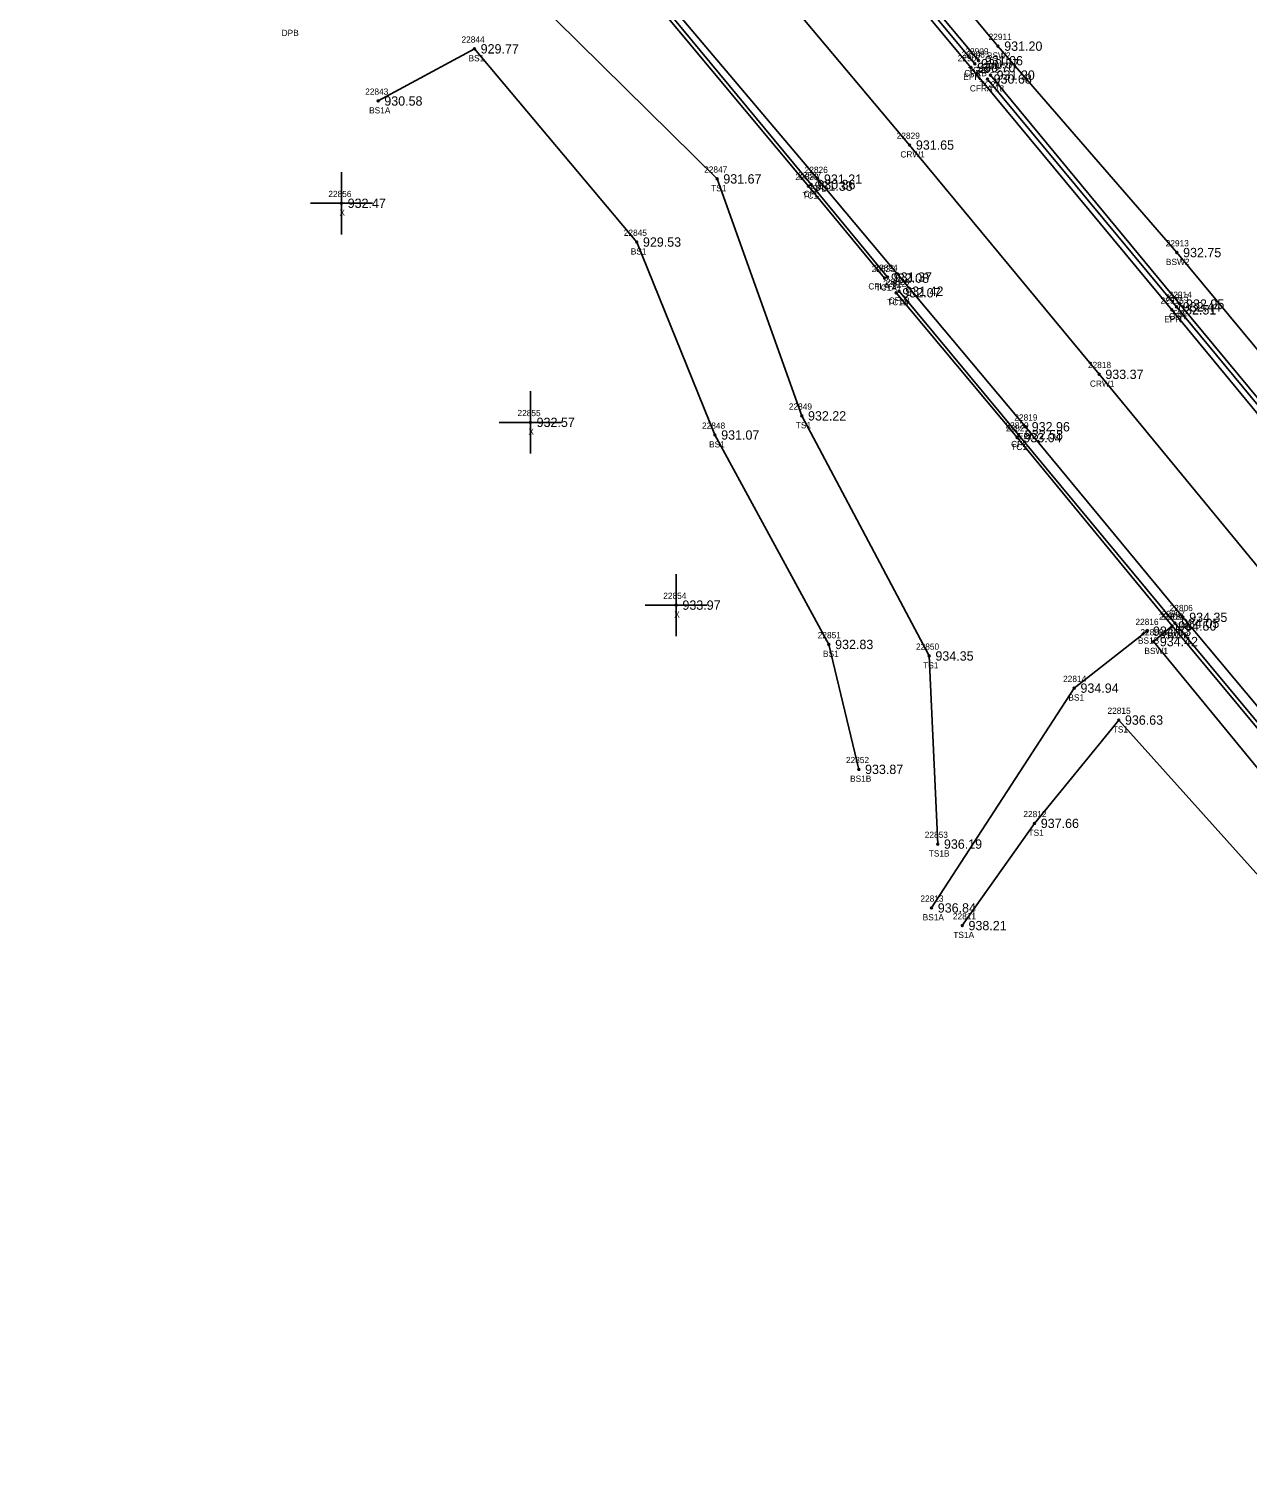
# Model space of a CAD drawing. Extents: x 1576181 to 1577685, y 1099396 to 1101490.
# Drawn here: x 1576232.8 to 1576428.7, y 1099850.9 to 1100084.5 of the extents above; entities that cross this region are included whole.
import ezdxf

# ---------------------------------------------------------------- set-up
doc = ezdxf.new("R2010")
doc.units = 0
for name, color, linetype in [('RD_DTM_BkLn1', 7, 'Continuous'), ('RD_DTM_BkLn2', 7, 'Continuous'), ('RD_DTM_BkLn_txCode', 7, 'Continuous'), ('RD_EX_Conc', 7, 'Continuous'), ('RD_EX_Conc_txCode', 7, 'Continuous'), ('RD_EX_Driveway_txCode', 7, 'Continuous'), ('RD_EX_Misc', 7, 'Continuous'), ('RD_EX_Misc_txCode', 7, 'Continuous'), ('RD_EX_Road', 7, 'Continuous'), ('RD_EX_Road_txCode', 7, 'Continuous'), ('RD_EX_TX_Conc_ELEV', 7, 'Continuous'), ('RD_EX_TX_Misc_ELEV', 7, 'Continuous'), ('RD_EX_TX_Road_ELEV', 7, 'Continuous'), ('RD_HC_Survey_ELEV', 7, 'Continuous'), ('RD_HC_Survey_txCode', 7, 'Continuous'), ('RD_SMD_Locator', 7, 'Continuous')]:
    doc.layers.add(name, color=color, linetype=linetype)

msp = doc.modelspace()

# ---------------------------------------------------------------- linework, layer by layer
at = {"layer": 'RD_DTM_BkLn1'}
msp.add_lwpolyline([(1576552.2, 1099850.88), (1576529.87, 1099877.59), (1576499.35, 1099914.67), (1576467.87, 1099952.97), (1576435.79, 1099991.46), (1576404.79, 1100029.02), (1576374.33, 1100065.86), (1576340.53, 1100106.05), (1576310.27, 1100142.66), (1576276.25, 1100183.58), (1576243.14, 1100223.05)], dxfattribs=at)
at = {"layer": 'RD_DTM_BkLn2'}
for points in [[(1576257.4, 1100233.36), (1576289.16, 1100194.59), (1576321.56, 1100155.93), (1576353.74, 1100117.24), (1576385.41, 1100079.42)], [(1576370.31, 1100044.47), (1576358.04, 1100059.26), (1576326.91, 1100096.57), (1576310.67, 1100115.96)], [(1576306.3, 1100096.99), (1576343.37, 1100060.42), (1576356.99, 1100022.34), (1576377.47, 1099983.76), (1576378.84, 1099953.53)], [(1576288.87, 1100072.94), (1576304.36, 1100081.32), (1576330.45, 1100050.27), (1576343.03, 1100019.27), (1576361.35, 1099985.61), (1576366.16, 1099965.54)], [(1576387.31, 1100077.1), (1576417.77, 1100040.31), (1576449.29, 1100002.34), (1576481.27, 1099963.75), (1576512.83, 1099926.03), (1576537.62, 1099896.34), (1576545.23, 1099890.59), (1576552.64, 1099888.11), (1576559.01, 1099887.38), (1576563.78, 1099887.59)], [(1576459.19, 1099937.38), (1576416.51, 1099988.58), (1576391.62, 1100018.84), (1576372.16, 1100042.12)], [(1576377.85, 1099943.27), (1576400.79, 1099978.59), (1576412.45, 1099987.74)], [(1576382.79, 1099940.43), (1576394.41, 1099956.86), (1576407.94, 1099973.46), (1576450.18, 1099926.39)]]:
    msp.add_lwpolyline(points, dxfattribs=at)
at = {"layer": 'RD_EX_Conc'}
for points in [[(1576260.63, 1100235.68), (1576292.32, 1100197.24), (1576324.7, 1100158.41), (1576356.89, 1100119.84), (1576388.53, 1100081.75), (1576417.29, 1100048.58), (1576453.09, 1100005.48), (1576485.23, 1099966.78), (1576516.75, 1099929.08), (1576537.53, 1099904.47)], [(1576256.92, 1100232.94), (1576288.76, 1100194.24), (1576321.1, 1100155.62), (1576353.2, 1100116.85), (1576384.81, 1100078.92)], [(1576370.77, 1100044.65), (1576358.48, 1100059.51), (1576327.45, 1100097.03), (1576315.3, 1100111.52), (1576315.3, 1100111.52), (1576311.1, 1100116.47)], [(1576386.83, 1100076.47), (1576417.24, 1100039.86), (1576448.62, 1100001.94), (1576480.86, 1099963.28), (1576512.43, 1099925.58), (1576537.17, 1099895.97), (1576544.94, 1099889.99), (1576552.63, 1099887.59), (1576559.14, 1099887.04), (1576563.8, 1099887.09)], [(1576459.68, 1099937.85), (1576416.98, 1099989.02), (1576391.85, 1100019.32), (1576372.62, 1100042.37)], [(1576452.41, 1099925.37), (1576456.22, 1099930.46), (1576454.77, 1099932.3), (1576456.21, 1099934.19), (1576413.55, 1099986.07), (1576416.51, 1099988.58)]]:
    msp.add_lwpolyline(points, dxfattribs=at)
at = {"layer": 'RD_EX_Misc'}
for p, q in [((1576282.98, 1100051.5), (1576282.98, 1100061.5)), ((1576277.98, 1100056.5), (1576287.98, 1100056.5)), ((1576313.36, 1100016.3), (1576313.36, 1100026.3)), ((1576308.36, 1100021.3), (1576318.36, 1100021.3)), ((1576336.8, 1099986.93), (1576336.8, 1099996.93)), ((1576331.8, 1099991.93), (1576341.8, 1099991.93))]:
    msp.add_line(p, q, dxfattribs=at)
at = {"layer": 'RD_EX_Road'}
for points in [[(1576256.11, 1100232.37), (1576288, 1100193.74), (1576320.42, 1100155.1), (1576352.59, 1100116.23), (1576384.18, 1100078.33), (1576416.49, 1100039.38), (1576447.98, 1100001.18), (1576479.99, 1099962.6), (1576511.56, 1099924.96), (1576536.28, 1099895.31), (1576544.58, 1099889.25), (1576552.5, 1099886.45), (1576559.41, 1099885.67), (1576563.94, 1099885.9), (1576563.8, 1099887.09)], [(1576526.76, 1099857.36), (1576527.6, 1099858), (1576488.54, 1099905.39), (1576460.88, 1099939.06), (1576418.27, 1099989.97), (1576392.95, 1100020.59), (1576359.55, 1100060.38), (1576328.02, 1100097.72), (1576316.02, 1100112.1), (1576316.51, 1100112.71), (1576297.48, 1100135.6), (1576269.79, 1100169.04), (1576232.76, 1100213.96)]]:
    msp.add_lwpolyline(points, dxfattribs=at)
at = {"layer": 'RD_SMD_Locator'}
for centre in [(1576388.53, 1100081.75), (1576304.36, 1100081.32), (1576385.41, 1100079.42), (1576384.18, 1100078.33), (1576384.81, 1100078.92), (1576387.31, 1100077.1), (1576386.83, 1100076.47), (1576288.87, 1100072.94), (1576374.33, 1100065.86), (1576343.37, 1100060.42), (1576358.04, 1100059.26), (1576358.48, 1100059.51), (1576359.55, 1100060.38), (1576282.98, 1100056.5), (1576330.45, 1100050.27), (1576417.29, 1100048.58), (1576370.31, 1100044.47), (1576370.77, 1100044.65), (1576372.16, 1100042.12), (1576372.62, 1100042.37), (1576417.24, 1100039.86), (1576417.77, 1100040.31), (1576416.49, 1100039.38), (1576404.79, 1100029.02), (1576313.36, 1100021.3), (1576356.99, 1100022.34), (1576343.03, 1100019.27), (1576391.62, 1100018.84), (1576391.85, 1100019.32), (1576392.95, 1100020.59), (1576336.8, 1099991.93), (1576416.51, 1099988.58), (1576416.51, 1099988.58), (1576416.98, 1099989.02), (1576418.27, 1099989.97), (1576412.45, 1099987.74), (1576413.55, 1099986.07), (1576361.35, 1099985.61), (1576377.47, 1099983.76), (1576400.79, 1099978.59), (1576407.94, 1099973.46), (1576366.16, 1099965.54), (1576394.41, 1099956.86), (1576378.84, 1099953.53), (1576377.85, 1099943.27), (1576382.79, 1099940.43)]:
    msp.add_circle(centre, 0.15, dxfattribs=at)

# ---------------------------------------------------------------- texts
at = {"layer": 'RD_DTM_BkLn_txCode'}
for s, p in [('22844', (1576302.28, 1100082.32)), ('BS1', (1576303.41, 1100079.32)), ('22843', (1576286.79, 1100073.94)), ('BS1A', (1576287.43, 1100070.94)), ('22847', (1576341.29, 1100061.42)), ('TS1', (1576342.41, 1100058.42)), ('22845', (1576328.37, 1100051.27)), ('BS1', (1576329.5, 1100048.27)), ('22849', (1576354.91, 1100023.34)), ('22848', (1576340.95, 1100020.27)), ('TS1', (1576356.03, 1100020.34)), ('BS1', (1576342.08, 1100017.27)), ('22816', (1576410.63, 1099988.74)), ('22851', (1576359.55, 1099986.61)), ('BS1B', (1576411.03, 1099985.74)), ('BS1', (1576360.4, 1099983.61)), ('22850', (1576375.35, 1099984.76)), ('TS1', (1576376.51, 1099981.76)), ('22814', (1576399, 1099979.59)), ('BS1', (1576399.85, 1099976.59)), ('22815', (1576406.14, 1099974.46)), ('TS1', (1576406.98, 1099971.46)), ('22852', (1576364.09, 1099966.54)), ('BS1B', (1576364.75, 1099963.54)), ('22812', (1576392.61, 1099957.86)), ('TS1', (1576393.44, 1099954.86)), ('22853', (1576376.76, 1099954.53)), ('TS1B', (1576377.4, 1099951.53)), ('22813', (1576376.06, 1099944.27)), ('BS1A', (1576376.42, 1099941.27)), ('22811', (1576381.28, 1099941.43)), ('TS1A', (1576381.35, 1099938.43))]:
    msp.add_text(s, height=1, dxfattribs=at).set_placement(p)
at = {"layer": 'RD_EX_Conc_txCode'}
for s, p in [('22911', (1576387.02, 1100082.75)), ('22908', (1576382.7, 1100079.92)), ('22909', (1576383.29, 1100080.42)), ('BSW2', (1576386.76, 1100079.75)), ('CFRB', (1576383.11, 1100076.92)), ('TC2B', (1576383.69, 1100077.42)), ('22912', (1576385.04, 1100077.47)), ('22910', (1576385.47, 1100078.1)), ('CFRA 18', (1576384.01, 1100074.47)), ('TC2A', (1576385.57, 1100075.1)), ('22828', (1576355.96, 1100060.26)), ('22827', (1576356.4, 1100060.51)), ('CFL', (1576357.28, 1100057.51)), ('TC1', (1576357.08, 1100057.26)), ('22913', (1576415.5, 1100049.58)), ('BSW2', (1576415.53, 1100046.58)), ('22825', (1576368.23, 1100045.47)), ('22824', (1576368.69, 1100045.65)), ('CFLA 24', (1576367.69, 1100042.65)), ('TC1A', (1576368.86, 1100042.47)), ('22822', (1576370.08, 1100043.12)), ('22823', (1576370.54, 1100043.37)), ('22914', (1576415.97, 1100041.31)), ('TC1B', (1576370.73, 1100040.12)), ('CFLB', (1576370.95, 1100040.37)), ('22915', (1576415.44, 1100040.86)), ('CFR', (1576416.01, 1100037.86)), ('TC2', (1576416.52, 1100038.31)), ('22820', (1576389.73, 1100020.32)), ('22821', (1576389.82, 1100019.84)), ('TC1', (1576390.66, 1100016.84)), ('CFL', (1576390.64, 1100017.32)), ('22807', (1576414.87, 1099990.02)), ('22809', (1576414.39, 1099989.58)), ('22810', (1576414.67, 1099989.58)), ('22808', (1576411.43, 1099987.07)), ('BSW1B', (1576414.55, 1099986.58)), ('TC1', (1576415.54, 1099986.58)), ('CFL', (1576415.78, 1099987.02)), ('BSW1', (1576412.07, 1099984.07))]:
    msp.add_text(s, height=1, dxfattribs=at).set_placement(p)
at = {"layer": 'RD_EX_Driveway_txCode'}
msp.add_text('DPB', height=1, dxfattribs=at).set_placement((1576273.36, 1100083.38))
at = {"layer": 'RD_EX_Misc_txCode'}
for s, p in [('22856', (1576280.87, 1100057.5)), ('X', (1576282.66, 1100054.5)), ('22855', (1576311.28, 1100022.3)), ('X', (1576313.04, 1100019.3)), ('22854', (1576334.72, 1099992.93)), ('X', (1576336.48, 1099989.93))]:
    msp.add_text(s, height=1, dxfattribs=at).set_placement(p)
at = {"layer": 'RD_EX_Road_txCode'}
for s, p in [('22907', (1576382.06, 1100079.33)), ('EPR', (1576382.95, 1100076.33)), ('22826', (1576357.45, 1100061.38)), ('EPL', (1576358.34, 1100058.38)), ('22916', (1576414.67, 1100040.38)), ('EPR', (1576415.26, 1100037.38)), ('22819', (1576391.16, 1100021.59)), ('EPL', (1576391.75, 1100018.59)), ('22806', (1576416.13, 1099990.97)), ('EPL', (1576417.06, 1099987.97))]:
    msp.add_text(s, height=1, dxfattribs=at).set_placement(p)
at = {"layer": 'RD_EX_TX_Conc_ELEV'}
for s, p in [('931.20', (1576389.53, 1100081)), ('930.57', (1576385.81, 1100078.17)), ('931.06', (1576386.41, 1100078.67)), ('930.68', (1576387.83, 1100075.72)), ('931.20', (1576388.31, 1100076.35)), ('931.33', (1576359.04, 1100058.51)), ('930.86', (1576359.48, 1100058.76)), ('932.75', (1576418.29, 1100047.83)), ('932.08', (1576371.31, 1100043.72)), ('931.37', (1576371.77, 1100043.9)), ('932.07', (1576373.16, 1100041.37)), ('931.42', (1576373.62, 1100041.62)), ('932.44', (1576418.24, 1100039.11)), ('932.95', (1576418.77, 1100039.56)), ('933.04', (1576392.62, 1100018.09)), ('932.58', (1576392.85, 1100018.57)), ('934.50', (1576417.51, 1099987.83)), ('934.50', (1576417.51, 1099987.83)), ('934.05', (1576417.98, 1099988.27)), ('934.42', (1576414.55, 1099985.32))]:
    msp.add_text(s, height=1.5, dxfattribs=at).set_placement(p)
at = {"layer": 'RD_EX_TX_Misc_ELEV'}
for s, p in [('929.77', (1576305.36, 1100080.57)), ('930.58', (1576289.87, 1100072.19)), ('931.67', (1576344.37, 1100059.67)), ('932.47', (1576283.98, 1100055.75)), ('929.53', (1576331.45, 1100049.52)), ('932.57', (1576314.36, 1100020.55)), ('932.22', (1576357.99, 1100021.59)), ('931.07', (1576344.03, 1100018.52)), ('933.97', (1576337.8, 1099991.18)), ('934.53', (1576413.45, 1099986.99)), ('932.83', (1576362.35, 1099984.86)), ('934.35', (1576378.47, 1099983.01)), ('934.94', (1576401.79, 1099977.84)), ('936.63', (1576408.94, 1099972.71)), ('933.87', (1576367.16, 1099964.79)), ('937.66', (1576395.41, 1099956.11)), ('936.19', (1576379.84, 1099952.78)), ('936.84', (1576378.85, 1099942.52)), ('938.21', (1576383.79, 1099939.68))]:
    msp.add_text(s, height=1.5, dxfattribs=at).set_placement(p)
at = {"layer": 'RD_EX_TX_Road_ELEV'}
for s, p in [('930.70', (1576385.18, 1100077.58)), ('931.21', (1576360.55, 1100059.63)), ('932.51', (1576417.49, 1100038.63)), ('932.96', (1576393.95, 1100019.84)), ('934.35', (1576419.27, 1099989.22))]:
    msp.add_text(s, height=1.5, dxfattribs=at).set_placement(p)
at = {"layer": 'RD_HC_Survey_ELEV'}
for s, p in [('931.65', (1576375.33, 1100065.11)), ('933.37', (1576405.79, 1100028.27))]:
    msp.add_text(s, height=1.5, dxfattribs=at).set_placement(p)
at = {"layer": 'RD_HC_Survey_txCode'}
for s, p in [('22829', (1576372.25, 1100066.86)), ('CRW1', (1576372.84, 1100063.86)), ('22818', (1576402.99, 1100030.02)), ('CRW1', (1576403.31, 1100027.02))]:
    msp.add_text(s, height=1, dxfattribs=at).set_placement(p)

doc.saveas('drawing.dxf')
